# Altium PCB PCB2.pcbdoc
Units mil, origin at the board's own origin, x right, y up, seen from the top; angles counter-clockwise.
Board outline 3818.9 x 3818.9 mil, 2 copper layers (Top Layer, Bottom Layer), stack 62.206 mil thick; 71 components, 12 nets, 142 pads, 0 vias.
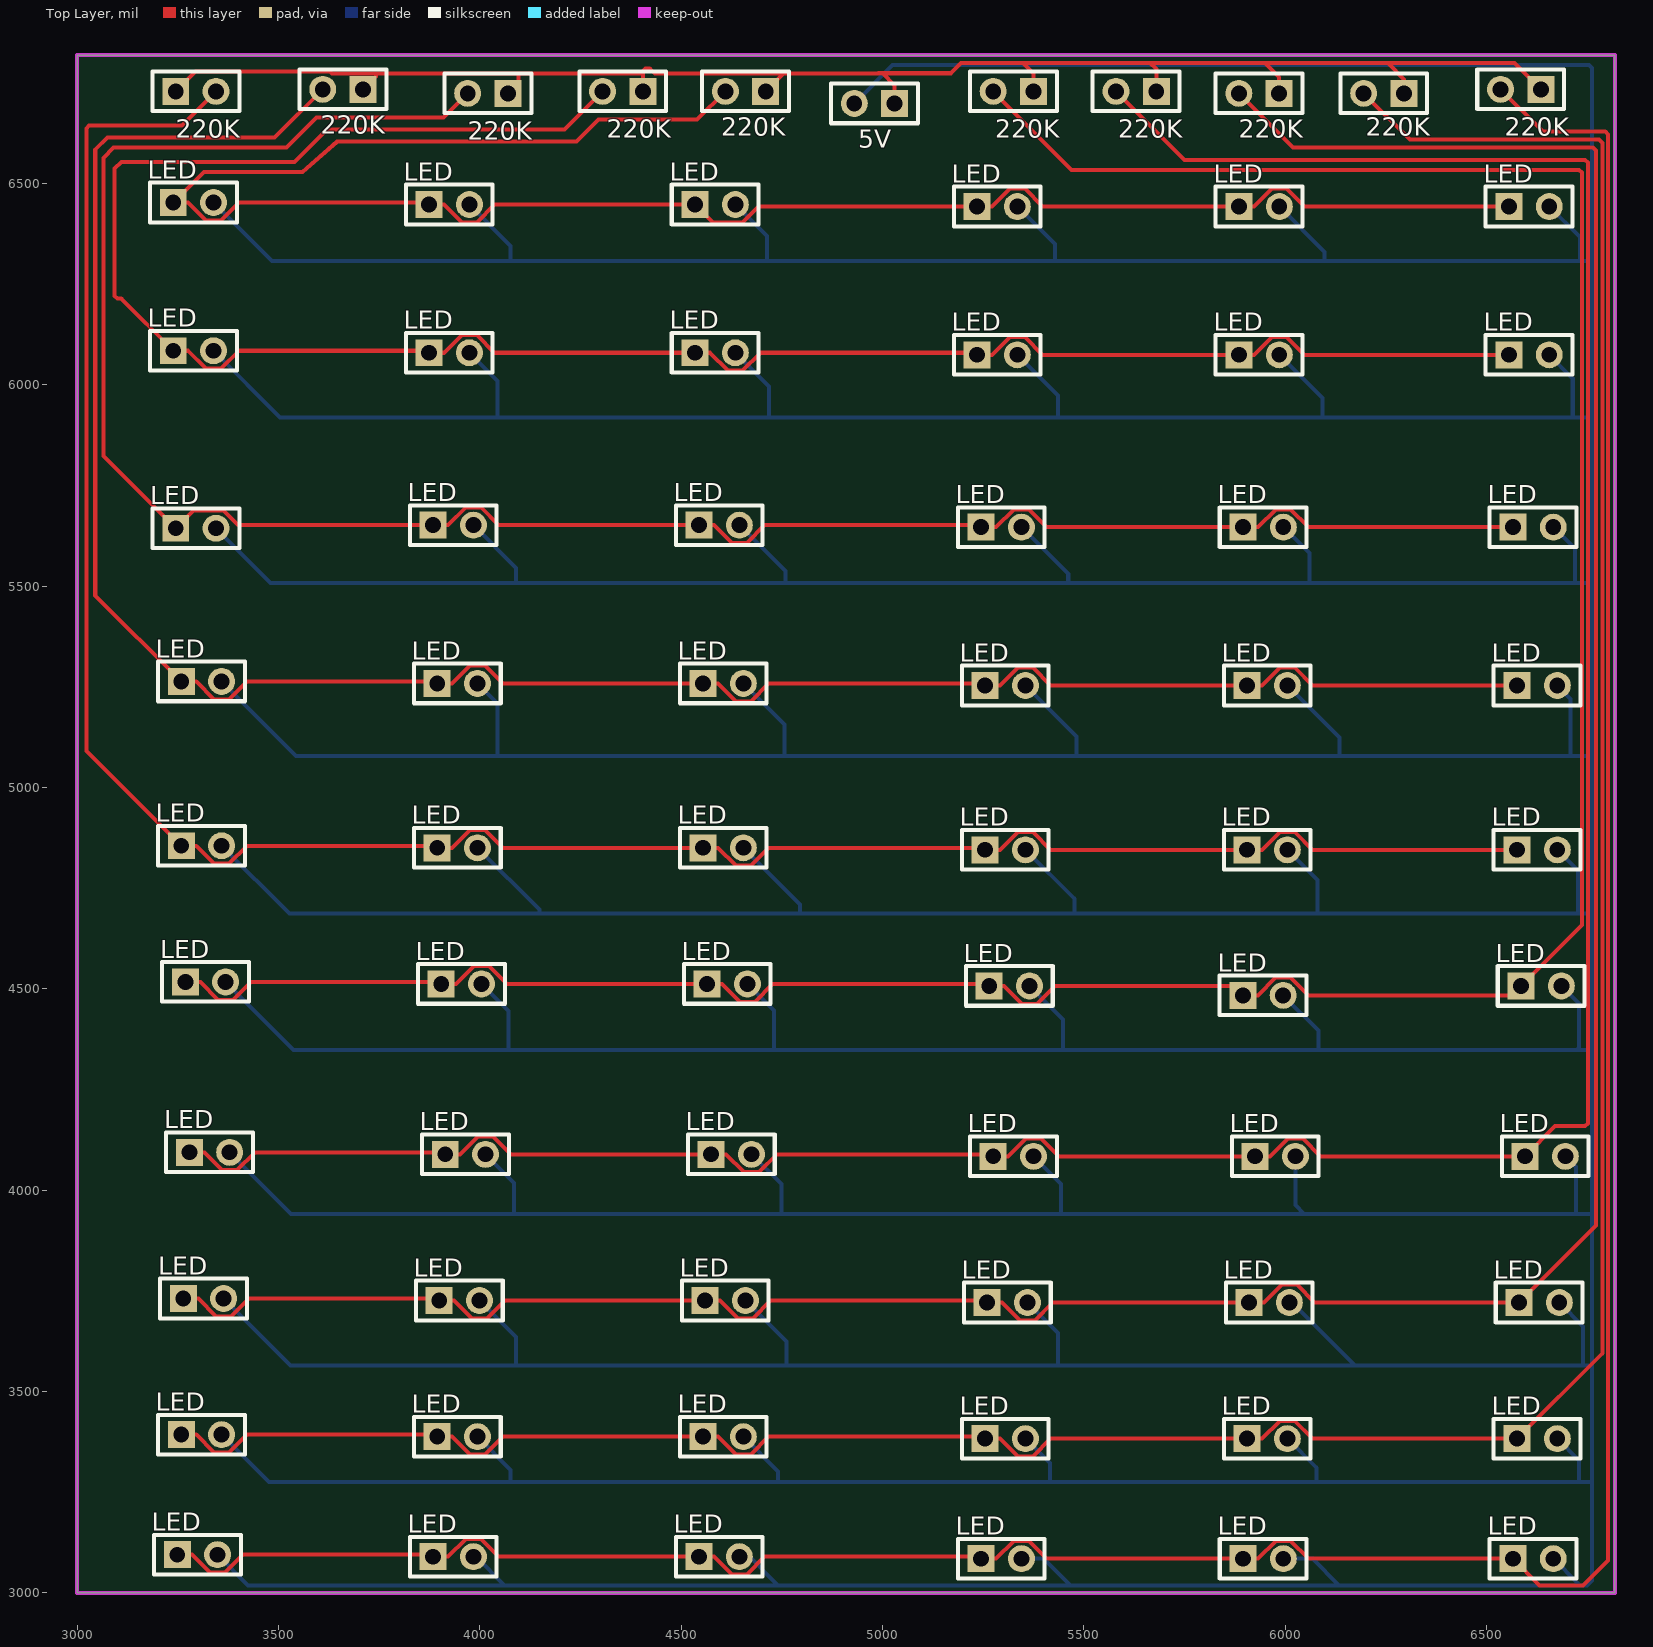
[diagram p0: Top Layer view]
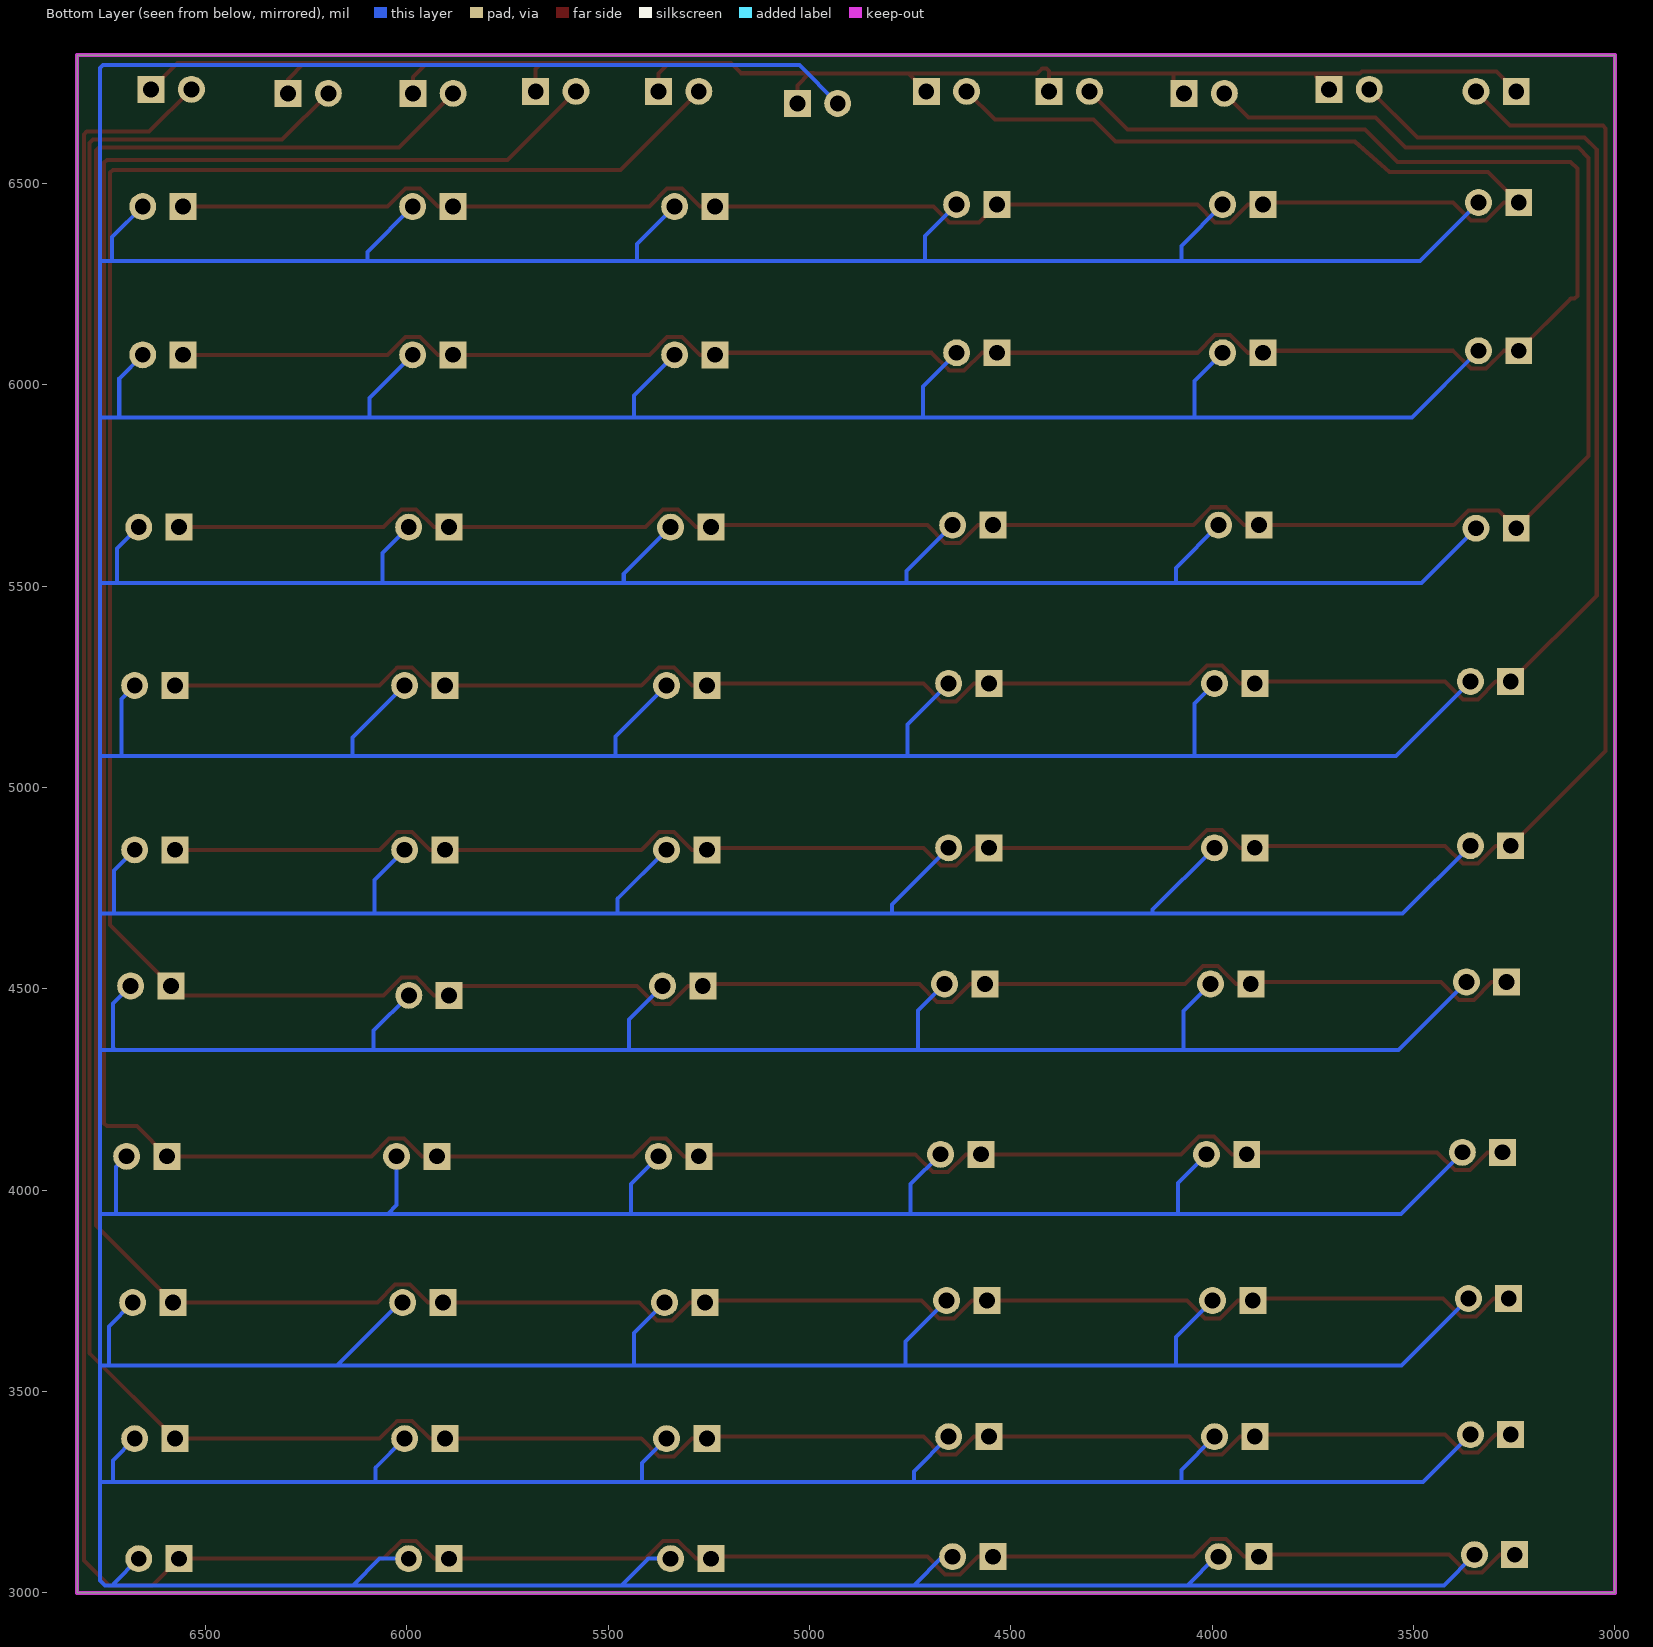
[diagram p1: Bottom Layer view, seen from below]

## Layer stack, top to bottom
Top Solder Mask Layer: solder mask 0.394, Dk 3.3
Top Layer: signal copper 1.379
Dielectric1: surface 59.449, FR4, Dk 4.5
Bottom Layer: signal copper 1.378
Bottom Solder Mask Layer: solder mask 0.394, Dk 3.3

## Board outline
3000,6818.9 3000,3000 6818.9,3000 6818.9,6818.9

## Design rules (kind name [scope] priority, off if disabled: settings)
BoardOutlineClearance copperThickness1oz [All] p0: genericclearance=10 ignorepadtopadclearanceinfootprint=FALSE except(0: Arc-SplitContinuation Track-SplitContinuation SMDPad-SplitContinuation THPad-SplitContinuation Via-SplitContinuation Fill-SplitContinuation Poly-SplitContinuation Region-SplitContinuation Text-SplitContinuation)
BoardOutlineClearance copperThickness2oz [All] p0: genericclearance=10 ignorepadtopadclearanceinfootprint=FALSE except(0: Arc-SplitContinuation Track-SplitContinuation SMDPad-SplitContinuation THPad-SplitContinuation Via-SplitContinuation Fill-SplitContinuation Poly-SplitContinuation Region-SplitContinuation Text-SplitContinuation)
BoardOutlineClearance otherClearance [All] p0: genericclearance=10 ignorepadtopadclearanceinfootprint=FALSE except(0: Arc-SplitContinuation Track-SplitContinuation SMDPad-SplitContinuation THPad-SplitContinuation Via-SplitContinuation Fill-SplitContinuation Poly-SplitContinuation Region-SplitContinuation Text-SplitContinuation)
Clearance copperThickness1oz [All] p1: gap=7 ignorepadtopadclearanceinfootprint=FALSE
Clearance copperThickness2oz [All] p1: gap=7 ignorepadtopadclearanceinfootprint=FALSE
Clearance otherClearance [All] p1: gap=7 ignorepadtopadclearanceinfootprint=FALSE
DiffPairsRouting differentialPair [All] p1: maxuncoupledlength=10 minlimit=6 maxlimit=Infinity mostfreqgap=6 toplayer_minwidth=5 toplayer_prefwidth=10 toplayer_maxwidth=100 bottomlayer_minwidth=5 bottomlayer_prefwidth=10 bottomlayer_maxwidth=100
PasteMaskExpansion pasteMaskExpansion [All] p1: expansion=0
PlaneConnect innerPlane [All] p1: planeconnectstyle=Relief reliefexpansion=20 reliefentries=4 reliefconductorwidth=10 reliefairgap=10
PolygonConnect copperRegion [All] p1: connectstyle=Relief reliefentries=4 reliefconductorwidth=10 polygonreliefangle="90 Angle" airgapwidth=10
RoutingVias viaSize [All] p1: viastyle="Through Hole" holewidth=12.0078 minholewidth=11.811 maxholewidth=248.0314 width=12.0078 minwidth=11.811 maxwidth=248.0314
SolderMaskExpansion solderMaskExpansion [IsVia] p1: useseparateexpansions=TRUE expansion=-1000 expansionbottom=-1000
SolderMaskExpansion solderMaskExpansion [All] p2: useseparateexpansions=TRUE expansion=2 expansionbottom=2
Width copperThickness1oz [All] p1: maxlimit=100 minlimit=5 preferedwidth=10
Width copperThickness2oz [All] p1: maxlimit=100 minlimit=8 preferedwidth=10

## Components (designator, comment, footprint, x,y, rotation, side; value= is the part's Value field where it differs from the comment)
5V "" HDR-TH_2P-P2.54-V-F 4980,6698.9 r180 top
220K "" HDR-TH_2P-P2.54-V-F 4660,6728.9 r180 top
220K "" HDR-TH_2P-P2.54-V-F 4355,6728.9 r180 top
220K "" HDR-TH_2P-P2.54-V-F 4020,6723.9 r180 top
220K "" HDR-TH_2P-P2.54-V-F 3660,6733.9 r180 top
220K "" HDR-TH_2P-P2.54-V-F 3295,6728.9 r0 top
220K "" HDR-TH_2P-P2.54-V-F 5325,6728.9 r180 top
220K "" HDR-TH_2P-P2.54-V-F 5630,6728.9 r180 top
220K "" HDR-TH_2P-P2.54-V-F 5935,6723.9 r180 top
220K "" HDR-TH_2P-P2.54-V-F 6245,6723.9 r180 top
220K "" HDR-TH_2P-P2.54-V-F 6585,6733.9 r180 top
LED "" HDR-TH_2P-P2.54-V-F 3288.74,6452.84 r0 top
LED "" HDR-TH_2P-P2.54-V-F 3924.17,6447.84 r0 top
LED "" HDR-TH_2P-P2.54-V-F 4584.61,6447.84 r0 top
LED "" HDR-TH_2P-P2.54-V-F 5285.04,6442.84 r0 top
LED "" HDR-TH_2P-P2.54-V-F 5935.47,6442.84 r0 top
LED "" HDR-TH_2P-P2.54-V-F 6605.9,6442.84 r0 top
LED "" HDR-TH_2P-P2.54-V-F 3288.74,6084.73 r0 top
LED "" HDR-TH_2P-P2.54-V-F 3924.17,6079.73 r0 top
LED "" HDR-TH_2P-P2.54-V-F 4584.61,6079.73 r0 top
LED "" HDR-TH_2P-P2.54-V-F 5285.04,6074.73 r0 top
LED "" HDR-TH_2P-P2.54-V-F 5935.47,6074.73 r0 top
LED "" HDR-TH_2P-P2.54-V-F 6605.9,6074.73 r0 top
LED "" HDR-TH_2P-P2.54-V-F 3295,5643.9 r0 top
LED "" HDR-TH_2P-P2.54-V-F 3934.17,5651.62 r0 top
LED "" HDR-TH_2P-P2.54-V-F 4594.61,5651.62 r0 top
LED "" HDR-TH_2P-P2.54-V-F 5295.04,5646.62 r0 top
LED "" HDR-TH_2P-P2.54-V-F 5945.47,5646.62 r0 top
LED "" HDR-TH_2P-P2.54-V-F 6615.9,5646.62 r0 top
LED "" HDR-TH_2P-P2.54-V-F 3308.74,5263.51 r0 top
LED "" HDR-TH_2P-P2.54-V-F 3944.17,5258.51 r0 top
LED "" HDR-TH_2P-P2.54-V-F 4604.61,5258.51 r0 top
LED "" HDR-TH_2P-P2.54-V-F 5305.04,5253.51 r0 top
LED "" HDR-TH_2P-P2.54-V-F 5955.47,5253.51 r0 top
LED "" HDR-TH_2P-P2.54-V-F 6625.9,5253.51 r0 top
LED "" HDR-TH_2P-P2.54-V-F 3308.74,4855.4 r0 top
LED "" HDR-TH_2P-P2.54-V-F 3944.17,4850.4 r0 top
LED "" HDR-TH_2P-P2.54-V-F 4604.61,4850.4 r0 top
LED "" HDR-TH_2P-P2.54-V-F 5305.04,4845.4 r0 top
LED "" HDR-TH_2P-P2.54-V-F 5955.47,4845.4 r0 top
LED "" HDR-TH_2P-P2.54-V-F 6625.9,4845.4 r0 top
LED "" HDR-TH_2P-P2.54-V-F 3318.74,4517.29 r0 top
LED "" HDR-TH_2P-P2.54-V-F 3954.17,4512.29 r0 top
LED "" HDR-TH_2P-P2.54-V-F 4614.61,4512.29 r0 top
LED "" HDR-TH_2P-P2.54-V-F 5315.04,4507.29 r0 top
LED "" HDR-TH_2P-P2.54-V-F 5945,4483.9 r0 top
LED "" HDR-TH_2P-P2.54-V-F 6635.9,4507.29 r0 top
LED "" HDR-TH_2P-P2.54-V-F 3328.74,4094.18 r0 top
LED "" HDR-TH_2P-P2.54-V-F 3964.17,4089.18 r0 top
LED "" HDR-TH_2P-P2.54-V-F 4624.61,4089.18 r0 top
LED "" HDR-TH_2P-P2.54-V-F 5325.04,4084.18 r0 top
LED "" HDR-TH_2P-P2.54-V-F 5975.47,4084.18 r0 top
LED "" HDR-TH_2P-P2.54-V-F 6645.9,4084.18 r0 top
LED "" HDR-TH_2P-P2.54-V-F 3313.74,3731.07 r0 top
LED "" HDR-TH_2P-P2.54-V-F 3949.17,3726.07 r0 top
LED "" HDR-TH_2P-P2.54-V-F 4609.61,3726.07 r0 top
LED "" HDR-TH_2P-P2.54-V-F 5310.04,3721.07 r0 top
LED "" HDR-TH_2P-P2.54-V-F 5960.47,3721.07 r0 top
LED "" HDR-TH_2P-P2.54-V-F 6630.9,3721.07 r0 top
LED "" HDR-TH_2P-P2.54-V-F 3308.74,3392.96 r0 top
LED "" HDR-TH_2P-P2.54-V-F 3944.17,3387.96 r0 top
LED "" HDR-TH_2P-P2.54-V-F 4604.61,3387.96 r0 top
LED "" HDR-TH_2P-P2.54-V-F 5305.04,3382.96 r0 top
LED "" HDR-TH_2P-P2.54-V-F 5955.47,3382.96 r0 top
LED "" HDR-TH_2P-P2.54-V-F 6625.9,3382.96 r0 top
LED "" HDR-TH_2P-P2.54-V-F 3298.74,3094.85 r0 top
LED "" HDR-TH_2P-P2.54-V-F 3934.17,3089.85 r0 top
LED "" HDR-TH_2P-P2.54-V-F 4594.61,3089.85 r0 top
LED "" HDR-TH_2P-P2.54-V-F 5295.04,3084.85 r0 top
LED "" HDR-TH_2P-P2.54-V-F 5945.47,3084.85 r0 top
LED "" HDR-TH_2P-P2.54-V-F 6615.9,3084.85 r0 top

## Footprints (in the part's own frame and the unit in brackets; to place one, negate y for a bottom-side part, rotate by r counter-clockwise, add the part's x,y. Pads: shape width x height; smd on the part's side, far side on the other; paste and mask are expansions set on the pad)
HDR-TH_2P-P2.54-V-F [mm]
  rect 1.7x1.7 hole 1: 1(-1.27,0)
  round 1.7 hole 1: 2(1.27,0)
  silkscreen extent -2.74,-1.25 2.74,1.25

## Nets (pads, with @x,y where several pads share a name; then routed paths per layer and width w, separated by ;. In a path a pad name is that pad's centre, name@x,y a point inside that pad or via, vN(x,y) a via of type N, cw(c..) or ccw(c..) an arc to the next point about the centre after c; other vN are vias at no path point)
$1N2: 5V.1 220K.1 | length 4109.6
  Top Layer w10: 220K.1@3245,6728.9 3294.45,6778.35 3628.41,6778.35 3633.41,6773.35 3741.83,6773.35 ; 220K.1@3710,6733.9 3741.83,6765.72 3741.83,6773.35 ; 220K.1@4070,6723.9 4096.51,6750.41 4096.51,6773.35 ; 220K.1@4405,6728.9 4405,6773.35 ; 220K.1@4710,6728.9 4754.45,6773.35 ; 5V.1 5030,6743.9 5000,6773.9 ; 220K.1@5375,6728.9 5375,6772.81 5348.91,6798.9 ; 220K.1@5680,6728.9 5680,6783.9 5665,6798.9 ; 220K.1@5985,6723.9 5985,6763.96 5950.06,6798.9 ; 220K.1@6295,6723.9 6295,6758.9 6255,6798.9 ; 220K.1@6635,6733.9 6570,6798.9 6255,6798.9 ; 3741.83,6773.35 4096.51,6773.35 ; 4096.51,6773.35 4405,6773.35 ; 4405,6773.35 4405,6778.9 4412.07,6785.97 4422.07,6785.97 4434.69,6773.35 4754.45,6773.35 ; 4754.45,6773.35 4989.45,6773.35 4990,6773.9 5000,6773.9 ; 5000,6773.9 5170,6773.9 5195,6798.9 5348.91,6798.9 ; 5348.91,6798.9 5665,6798.9 ; 5665,6798.9 5950.06,6798.9 ; 5950.06,6798.9 6255,6798.9
$1N7: 220K.2@3970,6723.9 LED.1@3245,5643.9 LED.1@3884.17,5651.62 LED.1@4544.61,5651.62 LED.1@5245.04,5646.62 LED.1@5895.47,5646.62 LED.1@6565.9,5646.62 | length 5469.7
  Top Layer w10: 220K.2@3970,6723.9 3910,6663.9 3595,6663.9 3520,6588.9 3090,6588.9 3065,6563.9 3065,5823.9 3245,5643.9 3289.45,5688.35 3363.41,5688.35 3400.14,5651.62 3884.17,5651.62 3921.31,5651.62 3965.76,5696.06 4002.58,5696.06 4047.03,5651.62 4544.61,5651.62 4581.75,5651.62 4626.19,5607.17 4663.02,5607.17 4707.47,5651.62 5240.04,5651.62 5245.04,5646.62 5282.18,5646.62 5326.63,5691.06 5363.45,5691.06 5407.9,5646.62 5895.47,5646.62 5932.61,5646.62 5977.06,5691.06 6013.88,5691.06 6058.33,5646.62 LED.1@6565.9,5646.62
$1N8: 220K.2@3610,6733.9 LED.1@3258.74,5263.51 LED.1@3894.17,5258.51 LED.1@4554.61,5258.51 LED.1@5255.04,5253.51 LED.1@5905.47,5253.51 LED.1@6575.9,5253.51 | length 5541.5
  Top Layer w10: 220K.2@3610,6733.9 3490,6613.9 3075,6613.9 3045,6583.9 3045,5477.25 3258.74,5263.51 3295.88,5263.51 3340.33,5219.06 3377.15,5219.06 3421.6,5263.51 3889.17,5263.51 3894.17,5258.51 3931.31,5258.51 3975.76,5302.95 4012.58,5302.95 4057.03,5258.51 4554.61,5258.51 4591.75,5258.51 4636.19,5214.06 4673.02,5214.06 4717.47,5258.51 5250.04,5258.51 5255.04,5253.51 5292.18,5253.51 5336.63,5297.95 5373.45,5297.95 5417.9,5253.51 5905.47,5253.51 5942.61,5253.51 5987.06,5297.95 6023.88,5297.95 6068.33,5253.51 LED.1@6575.9,5253.51
$1N9: 220K.2@3345,6728.9 LED.1@3258.74,4855.4 LED.1@3894.17,4850.4 LED.1@4554.61,4850.4 LED.1@5255.04,4845.4 LED.1@5905.47,4845.4 LED.1@6575.9,4845.4 | length 5744.7
  Top Layer w10: 220K.2@3345,6728.9 3260,6643.9 3030,6643.9 3022.93,6636.83 3022.93,5091.21 3258.74,4855.4 3295.88,4855.4 3340.33,4810.95 3377.15,4810.95 3421.6,4855.4 3889.17,4855.4 3894.17,4850.4 3931.31,4850.4 3975.76,4894.84 4012.58,4894.84 4057.03,4850.4 4554.61,4850.4 4591.75,4850.4 4636.19,4805.95 4673.02,4805.95 4717.47,4850.4 5250.04,4850.4 5255.04,4845.4 5292.18,4845.4 5336.63,4889.84 5373.45,4889.84 5417.9,4845.4 5905.47,4845.4 5942.61,4845.4 5987.06,4889.84 6023.88,4889.84 6068.33,4845.4 LED.1@6575.9,4845.4
$1N10: 220K.2@5275,6728.9 LED.1@3268.74,4517.29 LED.1@3904.17,4512.29 LED.1@4564.61,4512.29 LED.1@5265.04,4507.29 LED.1@5895,4483.9 LED.1@6585.9,4507.29 | length 7152.7
  Top Layer w10: LED.1@3268.74,4517.29 3305.88,4517.29 3350.33,4472.84 3387.15,4472.84 3431.6,4517.29 3899.17,4517.29 3904.17,4512.29 3941.31,4512.29 3985.76,4556.73 4022.58,4556.73 4067.03,4512.29 4564.61,4512.29 4601.75,4512.29 4646.19,4467.84 4683.02,4467.84 4727.47,4512.29 5260.04,4512.29 5265.04,4507.29 5302.18,4507.29 5346.63,4462.84 5383.45,4462.84 5427.9,4507.29 5871.61,4507.29 5895,4483.9 5932.14,4483.9 5976.59,4528.35 6013.41,4528.35 6057.86,4483.9 6562.52,4483.9 6585.9,4507.29 6737.07,4658.45 6737.07,6526.83 6730,6533.9 5470,6533.9 220K.2@5275,6728.9
$1N11: 220K.2@5580,6728.9 LED.1@3278.74,4094.18 LED.1@3914.17,4089.18 LED.1@4574.61,4089.18 LED.1@5275.04,4084.18 LED.1@5925.47,4084.18 LED.1@6595.9,4084.18 | length 7326.7
  Top Layer w10: LED.1@3278.74,4094.18 3315.88,4094.18 3360.33,4049.73 3397.15,4049.73 3441.6,4094.18 3909.17,4094.18 3914.17,4089.18 3951.31,4089.18 3995.76,4133.62 4032.58,4133.62 4077.03,4089.18 4574.61,4089.18 4611.75,4089.18 4656.19,4044.73 4693.02,4044.73 4737.47,4089.18 5270.04,4089.18 5275.04,4084.18 5312.18,4084.18 5356.63,4128.62 5393.45,4128.62 5437.9,4084.18 5925.47,4084.18 5962.61,4084.18 6007.06,4128.62 6043.88,4128.62 6088.33,4084.18 6595.9,4084.18 6670.63,4158.9 6745,4158.9 6752.07,4165.97 6752.07,6551.83 6745,6558.9 5750,6558.9 220K.2@5580,6728.9
$1N12: 220K.2@5885,6723.9 LED.1@3263.74,3731.07 LED.1@3899.17,3726.07 LED.1@4559.61,3726.07 LED.1@5260.04,3721.07 LED.1@5910.47,3721.07 LED.1@6580.9,3721.07 | length 7391.3
  Top Layer w10: LED.1@3263.74,3731.07 3300.88,3731.07 3345.33,3686.62 3382.15,3686.62 3426.6,3731.07 3894.17,3731.07 3899.17,3726.07 3936.31,3726.07 3980.76,3681.62 4017.58,3681.62 4062.03,3726.07 4559.61,3726.07 4596.75,3726.07 4641.19,3681.62 4678.02,3681.62 4722.47,3726.07 5255.04,3726.07 5260.04,3721.07 5297.18,3721.07 5341.63,3676.62 5378.45,3676.62 5422.9,3721.07 5910.47,3721.07 5947.61,3721.07 5992.06,3765.51 6028.88,3765.51 6073.33,3721.07 6580.9,3721.07 6772.07,3912.23 6772.07,6581.83 6765,6588.9 6020,6588.9 220K.2@5885,6723.9
$1N16: 220K.2@6195,6723.9 LED.1@3258.74,3392.96 LED.1@3894.17,3387.96 LED.1@4554.61,3387.96 LED.1@5255.04,3382.96 LED.1@5905.47,3382.96 LED.1@6575.9,3382.96 | length 7455.2
  Top Layer w10: LED.1@3258.74,3392.96 3295.88,3392.96 3340.33,3348.51 3377.15,3348.51 3421.6,3392.96 3889.17,3392.96 3894.17,3387.96 3931.31,3387.96 3975.76,3343.51 4012.58,3343.51 4057.03,3387.96 4554.61,3387.96 4591.75,3387.96 4636.19,3343.51 4673.02,3343.51 4717.47,3387.96 5250.04,3387.96 5255.04,3382.96 5292.18,3382.96 5336.63,3338.51 5373.45,3338.51 5417.9,3382.96 5905.47,3382.96 5942.61,3382.96 5987.06,3427.4 6023.88,3427.4 6068.33,3382.96 6575.9,3382.96 6788.06,3595.11 6788.06,6600.84 6780,6608.9 6310,6608.9 220K.2@6195,6723.9
$1N21: 220K.2@4305,6728.9 LED.1@3238.74,6084.73 LED.1@3874.17,6079.73 LED.1@4534.61,6079.73 LED.1@5235.04,6074.73 LED.1@5885.47,6074.73 LED.1@6555.9,6074.73 | length 5315.2
  Top Layer w10: 220K.2@4305,6728.9 4210,6633.9 3620,6633.9 3540,6553.9 3110,6553.9 3092.93,6536.83 3092.93,6220.97 3100,6213.9 3109.57,6213.9 3238.74,6084.73 3275.88,6084.73 3320.33,6040.28 3357.15,6040.28 3401.6,6084.73 3869.17,6084.73 3874.17,6079.73 3911.31,6079.73 3955.76,6124.17 3992.58,6124.17 4037.03,6079.73 4534.61,6079.73 4571.75,6079.73 4616.19,6035.28 4653.02,6035.28 4697.47,6079.73 5230.04,6079.73 5235.04,6074.73 5272.18,6074.73 5316.63,6119.17 5353.45,6119.17 5397.9,6074.73 5885.47,6074.73 5922.61,6074.73 5967.06,6119.17 6003.88,6119.17 6048.33,6074.73 LED.1@6555.9,6074.73
$1N22: 220K.2@4610,6728.9 LED.1@3238.74,6452.84 LED.1@3874.17,6447.84 LED.1@4534.61,6447.84 LED.1@5235.04,6442.84 LED.1@5885.47,6442.84 LED.1@6555.9,6442.84 | length 4984.2
  Top Layer w10: 220K.2@4610,6728.9 4540,6658.9 4295,6658.9 4240,6603.9 3645,6603.9 3560,6528.9 3314.8,6528.9 3238.74,6452.84 3275.88,6452.84 3320.33,6408.39 3357.15,6408.39 3401.6,6452.84 3869.17,6452.84 3874.17,6447.84 3911.31,6447.84 3955.76,6403.39 3992.58,6403.39 4037.03,6447.84 4534.61,6447.84 4579.05,6403.39 4653.02,6403.39 4692.47,6442.84 5235.04,6442.84 5272.18,6442.84 5316.63,6487.28 5353.45,6487.28 5397.9,6442.84 5885.47,6442.84 5922.61,6442.84 5967.06,6487.28 6003.88,6487.28 6048.33,6442.84 LED.1@6555.9,6442.84
$1N23: 220K.2@6535,6733.9 LED.1@3248.74,3094.85 LED.1@3884.17,3089.85 LED.1@4544.61,3089.85 LED.1@5245.04,3084.85 LED.1@5895.47,3084.85 LED.1@6565.9,3084.85 | length 7649
  Top Layer w10: LED.1@3248.74,3094.85 3285.88,3094.85 3330.33,3050.4 3367.15,3050.4 3411.6,3094.85 3879.17,3094.85 3884.17,3089.85 3921.31,3089.85 3965.76,3134.29 4002.58,3134.29 4047.03,3089.85 4544.61,3089.85 4581.75,3089.85 4626.19,3045.4 4663.02,3045.4 4707.47,3089.85 5240.04,3089.85 5245.04,3084.85 5282.18,3084.85 5326.63,3129.29 5363.45,3129.29 5407.9,3084.85 5895.47,3084.85 5932.61,3084.85 5977.06,3129.29 6013.88,3129.29 6058.33,3084.85 6565.9,3084.85 6631.85,3018.9 6740,3018.9 6802.07,3080.97 6802.07,6621.83 6795,6628.9 6640,6628.9 220K.2@6535,6733.9
$1N25: 5V.2 LED.2 | length 49214.4
  Bottom Layer w10: LED.2@3338.74,6084.73 3504.08,5919.39 4043.72,5919.39 ; LED.2@3338.74,6452.84 3484.16,6307.41 4076.69,6307.41 ; LED.2@3345,5643.9 3480.36,5508.54 4758.9,5508.54 ; LED.2@3348.74,3094.85 3424.69,3018.9 4061.47,3018.9 ; LED.2@3358.74,3392.96 3476.21,3275.49 4076.69,3275.49 ; LED.2@3358.74,4855.4 3527.3,4686.83 4147.7,4686.83 ; LED.2@3358.74,5263.51 3543.58,5078.66 4043.72,5078.66 ; LED.2@3363.74,3731.07 3530.2,3564.6 4089.37,3564.6 ; LED.2@3368.74,4517.29 3537.76,4348.26 4071.62,4348.26 ; LED.2@3378.74,4094.18 3531.7,3941.22 4748.76,3941.22 ; LED.2@3974.17,6079.73 4043.72,6010.18 4043.72,5919.39 ; LED.2@3974.17,6447.84 4076.69,6345.32 4076.69,6307.41 ; LED.2@3984.17,3089.85 3990.52,3089.85 4061.47,3018.9 ; LED.2@3984.17,5651.62 4090,5545.79 4090,5513.9 ; LED.2@3994.17,3387.96 4076.69,3305.44 4076.69,3275.49 ; LED.2@3994.17,4850.4 4147.7,4696.87 4147.7,4686.83 ; LED.2@3994.17,5258.51 4043.72,5208.96 4043.72,5078.66 ; LED.2@3999.17,3726.07 4089.37,3635.87 4089.37,3564.6 ; LED.2@4004.17,4512.29 4071.62,4444.84 4071.62,4348.26 ; LED.2@4014.17,4089.18 4085,4018.35 4085,3948.9 ; LED.2@4634.61,6079.73 4718.32,5996.01 4718.32,5919.39 ; LED.2@4634.61,6447.84 4713.25,6369.19 4713.25,6307.41 ; LED.2@4644.61,3089.85 4670.2,3089.85 4741.15,3018.9 ; LED.2@4644.61,5651.62 4758.9,5537.32 4758.9,5508.54 ; LED.2@4654.61,3387.96 4741.15,3301.41 4741.15,3275.49 ; LED.2@4654.61,4850.4 4795,4710 4795,4686.83 ; LED.2@4654.61,5258.51 4756.37,5156.74 4756.37,5078.66 ; LED.2@4659.61,3726.07 4761.44,3624.23 4761.44,3564.6 ; LED.2@4664.61,4512.29 4731.01,4445.89 4731.01,4348.26 ; LED.2@4674.61,4089.18 4748.76,4015.02 4748.76,3941.22 ; 5V.2 5025,6793.9 6755,6793.9 6762.07,6786.83 6762.07,6307.41 ; LED.2@5335.04,6074.73 5436.04,5973.72 5436.04,5919.39 ; LED.2@5335.04,6442.84 5428.44,6349.44 5428.44,6307.41 ; LED.2@5345.04,3084.85 5400.53,3084.85 5466.48,3018.9 ; LED.2@5345.04,5646.62 5461.41,5530.25 5461.41,5508.54 ; LED.2@5355.04,3382.96 5415.76,3322.24 5415.76,3275.49 ; LED.2@5355.04,4845.4 5476.62,4723.81 5476.62,4686.83 ; LED.2@5355.04,5253.51 5481.69,5126.85 5481.69,5078.66 ; LED.2@5360.04,3721.07 5436.04,3645.06 5436.04,3564.6 ; LED.2@5365.04,4507.29 5448.73,4423.6 5448.73,4348.26 ; LED.2@5375.04,4084.18 5443.65,4015.56 5443.65,3941.22 ; LED.2@5985.47,6074.73 6092.9,5967.3 6092.9,5919.39 ; LED.2@5985.47,6442.84 6097.97,6330.34 6097.97,6307.41 ; LED.2@5995,4483.9 6082.75,4396.14 6082.75,4348.26 ; LED.2@5995.47,3084.85 6067.53,3084.85 6133.48,3018.9 ; LED.2@5995.47,5646.62 6060,5582.09 6060,5508.54 ; LED.2@6005.47,3382.96 6077.68,3310.75 6077.68,3275.49 ; LED.2@6005.47,4845.4 6080.22,4770.65 6080.22,4686.83 ; LED.2@6005.47,5253.51 6135,5123.98 6135,5078.66 ; LED.2@6010.47,3721.07 6017.59,3721.07 6174.05,3564.6 ; LED.2@6025.47,4084.18 6025.47,3962.99 6047.25,3941.22 ; LED.2@6655.9,6074.73 6714.25,6016.38 6714.25,5919.39 ; LED.2@6655.9,6442.84 6732,6366.74 6732,6307.41 ; LED.2@6665.9,3084.85 6726.93,3023.82 6726.93,3018.9 ; LED.2@6665.9,5646.62 6719.32,5593.2 6719.32,5508.54 ; LED.2@6675.9,3382.96 6730,3328.86 6730,3276.02 6729.46,3275.49 ; LED.2@6675.9,4845.4 6726.93,4794.37 6726.93,4686.83 ; LED.2@6675.9,5253.51 6709.17,5220.24 6709.17,5078.66 ; LED.2@6680.9,3721.07 6740,3661.97 6740,3564.6 ; LED.2@6685.9,4507.29 6730,4463.19 6730,4353.87 6724.39,4348.26 ; LED.2@6695.9,4084.18 6721.85,4058.23 6721.85,3941.22 ; 4043.72,5078.66 4756.37,5078.66 ; 4043.72,5919.39 4718.32,5919.39 ; 4061.47,3018.9 4741.15,3018.9 ; 4071.62,4348.26 4731.01,4348.26 ; 4076.69,3275.49 4741.15,3275.49 ; 4076.69,6307.41 4713.25,6307.41 ; 4089.37,3564.6 4761.44,3564.6 ; 4147.7,4686.83 4795,4686.83 ; 4713.25,6307.41 5428.44,6307.41 ; 4718.32,5919.39 5436.04,5919.39 ; 4731.01,4348.26 5448.73,4348.26 ; 4741.15,3018.9 5466.48,3018.9 ; 4741.15,3275.49 5415.76,3275.49 ; 4748.76,3941.22 5443.65,3941.22 ; 4756.37,5078.66 5481.69,5078.66 ; 4758.9,5508.54 5461.41,5508.54 ; 4761.44,3564.6 5436.04,3564.6 ; 4795,4686.83 5476.62,4686.83 ; 5415.76,3275.49 6077.68,3275.49 ; 5428.44,6307.41 6097.97,6307.41 ; 5436.04,3564.6 6174.05,3564.6 ; 5436.04,5919.39 6092.9,5919.39 ; 5443.65,3941.22 6047.25,3941.22 ; 5448.73,4348.26 6082.75,4348.26 ; 5461.41,5508.54 6060,5508.54 ; 5466.48,3018.9 6133.48,3018.9 ; 5476.62,4686.83 6080.22,4686.83 ; 5481.69,5078.66 6135,5078.66 ; 6047.25,3941.22 6721.85,3941.22 ; 6060,5508.54 6719.32,5508.54 ; 6077.68,3275.49 6729.46,3275.49 ; 6080.22,4686.83 6726.93,4686.83 ; 6082.75,4348.26 6724.39,4348.26 ; 6092.9,5919.39 6714.25,5919.39 ; 6097.97,6307.41 6732,6307.41 ; 6133.48,3018.9 6726.93,3018.9 ; 6135,5078.66 6709.17,5078.66 ; 6174.05,3564.6 6740,3564.6 ; 6709.17,5078.66 6762.07,5078.66 ; 6714.25,5919.39 6762.07,5919.39 ; 6719.32,5508.54 6762.07,5508.54 ; 6721.85,3941.22 6762.07,3941.22 ; 6724.39,4348.26 6762.07,4348.26 ; 6726.93,3018.9 6750,3018.9 6762.07,3030.97 6762.07,3275.49 ; 6726.93,4686.83 6762.07,4686.83 ; 6729.46,3275.49 6762.07,3275.49 ; 6732,6307.41 6762.07,6307.41 ; 6740,3564.6 6762.07,3564.6 ; 6762.07,3275.49 6762.07,3564.6 ; 6762.07,3564.6 6762.07,3941.22 ; 6762.07,3941.22 6762.07,4348.26 ; 6762.07,4348.26 6762.07,4686.83 ; 6762.07,4686.83 6762.07,5078.66 ; 6762.07,5078.66 6762.07,5508.54 ; 6762.07,5508.54 6762.07,5919.39 ; 6762.07,5919.39 6762.07,6307.41

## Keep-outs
Board Outline Layer:
  the board outline again, w10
